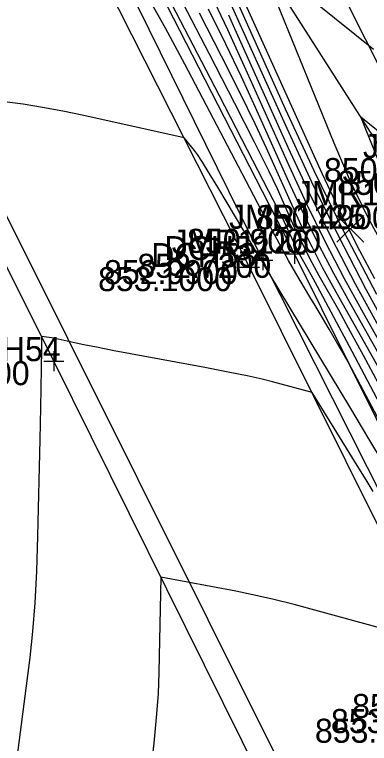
# Model space of a CAD drawing. Extents: x 1654928 to 1810050, y 486881 to 626330.
# Drawn here: x 1801410.28 to 1801428.02, y 489840.21 to 489876.6 of the extents above; entities that cross this region are included whole.
import ezdxf

# ---------------------------------------------------------------- set-up
doc = ezdxf.new("R2010")
doc.units = 0
for name, color, linetype in [('DR_X_Ditch', 7, 'Continuous'), ('DT_X_Contour_Major', 7, 'Continuous'), ('DT_X_Contour_Minor', 7, 'Continuous'), ('PV_X_EOP', 7, 'Continuous'), ('PV_X_Shoulder', 7, 'Continuous'), ('RW_X_Esmt_SH', 7, 'Continuous'), ('SV_X_Break_Lines', 7, 'Continuous'), ('SV_X_Center_of_Pavt', 7, 'Continuous'), ('SV_X_CL_Survey_20', 7, 'Continuous'), ('SV_X_Random_Point', 7, 'Continuous'), ('SV_X_Shot_Marker', 7, 'Continuous'), ('SV_X_Text_Elevation', 7, 'Continuous'), ('SV_X_Text_Name', 7, 'Continuous')]:
    doc.layers.add(name, color=color, linetype=linetype)

msp = doc.modelspace()

# ---------------------------------------------------------------- linework, layer by layer
at = {"layer": 'DR_X_Ditch'}
msp.add_lwpolyline([(1801442.185, 489846.735), (1801430.401, 489867.086), (1801416.556, 489888.735), (1801414.305, 489897.031)], dxfattribs=at)
at = {"layer": 'DT_X_Contour_Major'}
for points in [[(1801428.281, 489863.409), (1801427.532, 489864.802), (1801426.658, 489866.553), (1801425.657, 489868.661), (1801424.531, 489871.127), (1801421.359, 489878.179)], [(1801419.949, 489876.892), (1801420.818, 489875.143), (1801421.603, 489873.509), (1801422.304, 489871.987), (1801424.06, 489868.082), (1801424.74, 489866.618), (1801425.46, 489865.156), (1801426.221, 489863.696), (1801427.023, 489862.238), (1801429.216, 489858.352), (1801430.051, 489856.858), (1801430.914, 489855.292), (1801431.803, 489853.653), (1801432.719, 489851.942), (1801433.839, 489849.834)], [(1801428.768, 489854.125), (1801427.942, 489855.511), (1801427.087, 489856.934), (1801423.026, 489863.663), (1801422.744, 489864.117), (1801422.632, 489864.3), (1801422.418, 489864.656), (1801422.102, 489865.185), (1801421.684, 489865.885), (1801420.432, 489867.985), (1801420.008, 489868.69), (1801419.673, 489869.232), (1801419.428, 489869.61), (1801419.272, 489869.825), (1801418.758, 489870.446), (1801413.746, 489871.558), (1801412.692, 489871.78), (1801411.677, 489871.97), (1801410.702, 489872.129), (1801409.766, 489872.255)]]:
    msp.add_lwpolyline(points, dxfattribs=at)
at = {"layer": 'DT_X_Contour_Minor'}
for points in [[(1801416.257, 489881.862), (1801420.003, 489874.637), (1801421.269, 489872.185), (1801422.257, 489870.247), (1801422.967, 489868.824), (1801423.399, 489867.916), (1801424.179, 489866.18), (1801424.481, 489865.53), (1801424.801, 489864.88), (1801425.14, 489864.231), (1801425.496, 489863.583), (1801426.471, 489861.856), (1801426.962, 489860.967), (1801427.705, 489859.594), (1801428.699, 489857.739)], [(1801428.558, 489857.13), (1801427.147, 489859.782), (1801426.1, 489861.745), (1801425.417, 489863.021), (1801425.098, 489863.608), (1801424.733, 489864.256), (1801424.599, 489864.499), (1801424.472, 489864.742), (1801424.352, 489864.986), (1801424.239, 489865.229), (1801423.946, 489865.88), (1801423.649, 489866.482), (1801422.977, 489867.799), (1801421.929, 489869.831), (1801420.507, 489872.579), (1801416.213, 489880.859)], [(1801428.383, 489862.626), (1801426.776, 489865.709), (1801425.256, 489868.795), (1801423.822, 489871.885), (1801420.114, 489880.13)], [(1801428.837, 489864.845), (1801427.942, 489866.483), (1801427.08, 489868.264), (1801426.25, 489870.19), (1801422.453, 489879.514), (1801428.216, 489874.874)], [(1801420.099, 489877.591), (1801420.921, 489875.851), (1801421.756, 489874.023), (1801424.001, 489869.032), (1801424.869, 489867.162), (1801425.789, 489865.294), (1801426.761, 489863.429), (1801427.786, 489861.566), (1801430.588, 489856.6)], [(1801420.923, 489877.513), (1801423.882, 489870.934), (1801425.127, 489868.251), (1801426.447, 489865.571), (1801427.842, 489862.894), (1801429.312, 489860.221)], [(1801433.048, 489847.804), (1801427.009, 489859.164), (1801426.005, 489860.889), (1801425.784, 489861.267), (1801425.55, 489861.664), (1801425.303, 489862.077), (1801425.044, 489862.509), (1801424.335, 489863.684), (1801423.968, 489864.326), (1801423.398, 489865.369), (1801422.626, 489866.814), (1801421.652, 489868.662), (1801418.784, 489874.123), (1801417.823, 489875.924), (1801417.093, 489877.231)], [(1801419.5, 489876.695), (1801420.609, 489874.538), (1801421.538, 489872.695), (1801422.285, 489871.166), (1801422.851, 489869.952), (1801424.12, 489867.131), (1801424.61, 489866.074), (1801425.131, 489865.018), (1801425.68, 489863.964), (1801426.259, 489862.911), (1801427.843, 489860.104), (1801428.507, 489858.912), (1801429.309, 489857.443), (1801430.251, 489855.696), (1801431.332, 489853.671), (1801434.399, 489847.901), (1801435.435, 489845.956), (1801436.243, 489844.448), (1801436.822, 489843.379), (1801437.172, 489842.747), (1801437.802, 489841.646), (1801438.026, 489841.253)], [(1801420.964, 489876.597), (1801421.209, 489876.059), (1801423.941, 489869.983), (1801424.998, 489867.706), (1801426.118, 489865.432), (1801427.302, 489863.161), (1801428.549, 489860.893)], [(1801428.928, 489868.188), (1801427.581, 489871.496), (1801430.549, 489869.106)], [(1801428.21, 489852.798), (1801427.848, 489853.379), (1801427.49, 489853.955), (1801427.135, 489854.527), (1801425.148, 489857.731), (1801423.176, 489858.27), (1801422.648, 489858.4), (1801421.908, 489858.561), (1801420.956, 489858.753), (1801419.792, 489858.975), (1801415.263, 489859.821), (1801414.374, 489859.991), (1801413.74, 489860.115), (1801413.359, 489860.194), (1801412.451, 489860.394), (1801412.261, 489860.433), (1801412.114, 489860.46), (1801412.009, 489860.476), (1801411.621, 489860.523), (1801411.622, 489859.794), (1801411.62, 489859.68), (1801411.618, 489859.563), (1801411.612, 489859.249), (1801411.605, 489858.919), (1801411.564, 489856.99), (1801411.531, 489855.389), (1801411.428, 489850.557), (1801411.375, 489848.82), (1801411.292, 489847.232), (1801411.179, 489845.794), (1801411.036, 489844.506), (1801410.3, 489838.843)], [(1801431.386, 489845.203), (1801425.471, 489846.819), (1801424.262, 489847.14), (1801423.169, 489847.413), (1801422.192, 489847.636), (1801421.332, 489847.811), (1801417.589, 489848.509), (1801417.489, 489843.762), (1801417.447, 489842.69), (1801417.362, 489841.508), (1801417.236, 489840.216), (1801417.068, 489838.815)]]:
    msp.add_lwpolyline(points, dxfattribs=at)
at = {"layer": 'PV_X_EOP'}
msp.add_lwpolyline([(1801533.684, 489642.188), (1801522.484, 489664.508), (1801511.881, 489685.341), (1801500.299, 489708.684), (1801491.104, 489726.659), (1801480.832, 489747.383), (1801466.882, 489774.659), (1801456.506, 489795.715), (1801444.637, 489819.009), (1801433.258, 489841.444), (1801422.029, 489863.995), (1801410.905, 489885.928), (1801399.817, 489908.089), (1801388.576, 489930.656), (1801376.228, 489955.188), (1801366.008, 489975.62), (1801354.725, 489997.894)], dxfattribs=at)
at = {"layer": 'PV_X_Shoulder'}
msp.add_lwpolyline([(1801534.471, 489642.456), (1801522.963, 489664.954), (1801512.6, 489685.485), (1801500.973, 489709.112), (1801491.766, 489727.019), (1801481.526, 489747.768), (1801467.484, 489775.07), (1801457.116, 489796.092), (1801445.57, 489819.398), (1801434.029, 489841.927), (1801422.682, 489864.343), (1801411.885, 489886.25), (1801400.664, 489908.455), (1801366.703, 489976.232), (1801355.676, 489998.276)], dxfattribs=at)
at = {"layer": 'RW_X_Esmt_SH'}
msp.add_line((1801569.151, 489592.806), (1801345.762, 490039.449), dxfattribs=at)
at = {"layer": 'SV_X_Break_Lines'}
msp.add_lwpolyline([(1801445.791, 489822.136), (1801441.193, 489830.46), (1801435.211, 489842.68), (1801424.275, 489864.659), (1801412.811, 489886.984), (1801408.709, 489897.161), (1801400.001, 489913.183), (1801395.188, 489923.674), (1801385.653, 489941.642), (1801375.001, 489962.91), (1801364.942, 489983.144), (1801355.514, 490001.536)], dxfattribs=at)
at = {"layer": 'SV_X_Center_of_Pavt'}
msp.add_lwpolyline([(1801523.585, 489638.313), (1801512.853, 489659.481), (1801502.374, 489680.412), (1801490.819, 489703.952), (1801481.428, 489721.68), (1801470.803, 489742.834), (1801457.335, 489769.613), (1801446.389, 489792.464), (1801435.307, 489813.792), (1801423.54, 489836.522), (1801412.234, 489859.298), (1801401.202, 489881.345), (1801390.005, 489903.67), (1801378.784, 489926.715), (1801366.669, 489950.371), (1801356.567, 489970.63), (1801345.517, 489992.708)], dxfattribs=at)
at = {"layer": 'SV_X_CL_Survey_20'}
msp.add_line((1802886.975, 486913.246), (1801128.538, 490429.055), dxfattribs=at)
msp.add_line((1802886.975, 486913.246), (1801128.538, 490429.055), dxfattribs=at)
at = {"layer": 'SV_X_Random_Point'}
for p, q in [((1801426.396, 489865.239), (1801427.73, 489866.574)), ((1801426.396, 489866.574), (1801427.73, 489865.239))]:
    msp.add_line(p, q, dxfattribs=at)
at = {"layer": 'SV_X_Shot_Marker'}
for p, q in [((1801424.275, 489865.159), (1801424.275, 489864.159)), ((1801422.682, 489864.843), (1801422.682, 489863.843)), ((1801423.775, 489864.659), (1801424.775, 489864.659)), ((1801424.275, 489864.659), (1801424.275, 489864.659)), ((1801422.029, 489864.495), (1801422.029, 489863.495)), ((1801422.182, 489864.343), (1801423.182, 489864.343)), ((1801422.682, 489864.343), (1801422.682, 489864.343)), ((1801421.529, 489863.995), (1801422.529, 489863.995)), ((1801422.029, 489863.995), (1801422.029, 489863.995)), ((1801412.234, 489859.798), (1801412.234, 489858.798)), ((1801411.734, 489859.298), (1801412.734, 489859.298)), ((1801412.234, 489859.298), (1801412.234, 489859.298))]:
    msp.add_line(p, q, dxfattribs=at)

# ---------------------------------------------------------------- texts
at = {"layer": 'SV_X_Text_Elevation'}
for s, p in [('850.7500', (1801425.745, 489868.239)), ('850.6900', (1801426.411, 489867.6)), ('850.4900', (1801422.342, 489865.886)), ('850.9000', (1801418.9, 489864.707)), ('852.7200', (1801416.414, 489863.459)), ('852.9900', (1801414.746, 489863.143)), ('853.1000', (1801414.452, 489862.795)), ('853.2200', (1801404.335, 489858.098)), ('853.0400', (1801427.152, 489841.48)), ('853.3200', (1801426.093, 489840.727)), ('853.4600', (1801425.293, 489840.244))]:
    msp.add_text(s, height=1.2, dxfattribs=at).set_placement(p)
at = {"layer": 'SV_X_Text_Name'}
for s, p in [('JMR1123', (1801427.693, 489869.439)), ('JMR1124', (1801424.346, 489867.086)), ('JMR1125', (1801420.999, 489865.907)), ('JMR1126', (1801418.135, 489864.659)), ('DCH52', (1801417.769, 489864.343)), ('DCH53', (1801417.107, 489863.995)), ('DCH54', (1801407.321, 489859.298))]:
    msp.add_text(s, height=1.2, dxfattribs=at).set_placement(p)

doc.saveas('drawing.dxf')
